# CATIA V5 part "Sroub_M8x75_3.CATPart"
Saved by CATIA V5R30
Part number: Sroub_M8x75_3
Definition: E 1200_8x75
Nomenclature: E 1200_8x75
Source: Unknown
Description: PART--DESC
Bounding box of the stored display mesh (mm): x 123 to 136, y 12.01 to 24.99, z 11.2 to 94.2
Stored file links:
  E:\Bakalarka\Model\Forma_v7\Sroub_M8x75_3.CATPart
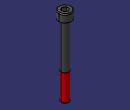
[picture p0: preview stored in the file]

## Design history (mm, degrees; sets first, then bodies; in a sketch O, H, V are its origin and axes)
Body1 "MANIFOLD_SOLID_BREP #3634" (main body)
  Solid1: solid without history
